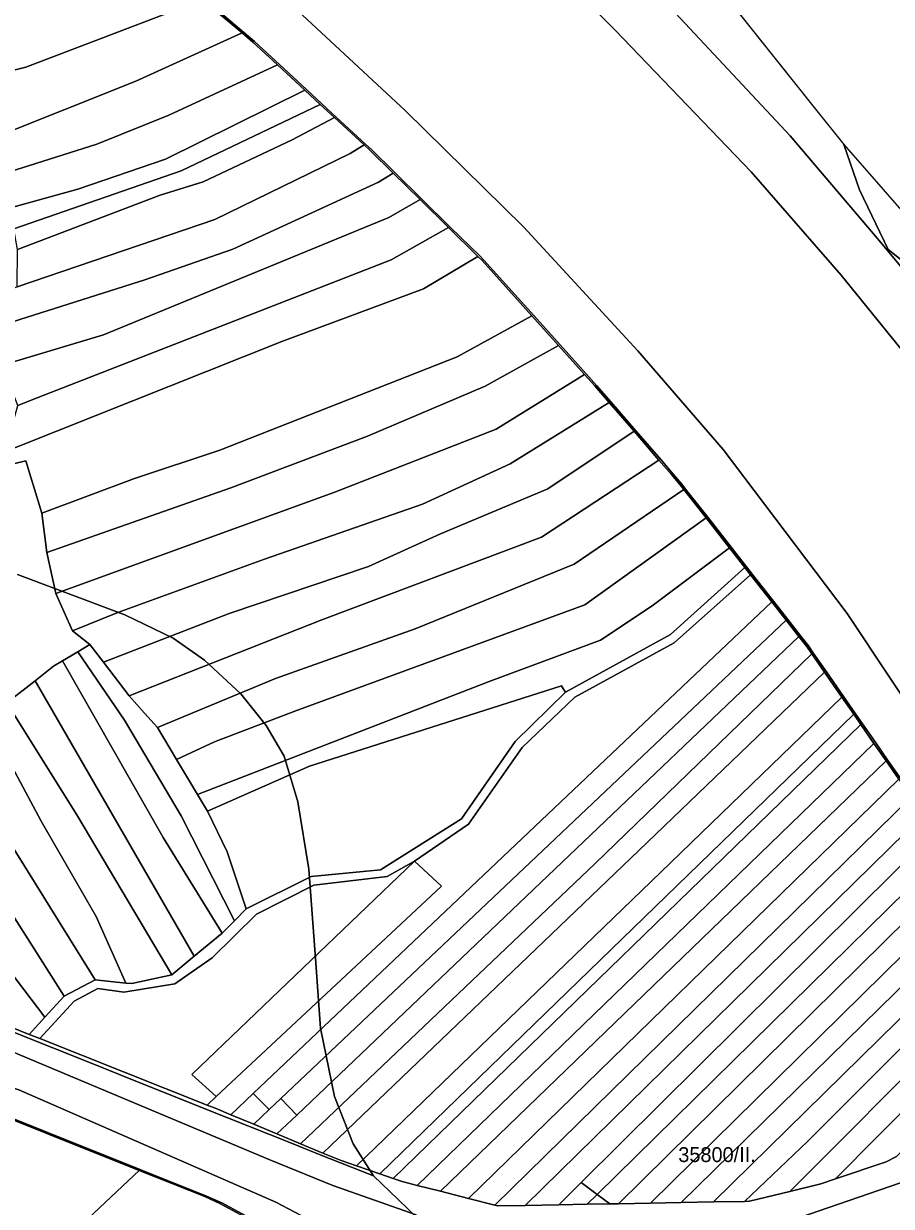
# Model space of a CAD drawing. Extents: x -535894 to -532834, y -1165802 to -1163645.
# Drawn here: x -533493.1 to -533201.8, y -1164904.7 to -1164507.5 of the extents above; entities that cross this region are included whole.
import ezdxf

# ---------------------------------------------------------------- set-up
doc = ezdxf.new("R2010")
doc.units = 0
for name, color, linetype in [('95560013', 7, 'Continuous'), ('95620013', 7, 'Continuous'), ('95630013', 7, 'Continuous'), ('95640013', 7, 'Continuous'), ('95660013', 7, 'Continuous')]:
    doc.layers.add(name, color=color, linetype=linetype)

msp = doc.modelspace()

# ---------------------------------------------------------------- linework, layer by layer
at = {"layer": '95560013'}
for points in [[(-533447.72, -1164486.86), (-533433.01, -1164499.36), (-533492.42, -1164522.13), (-533506.35, -1164525.6), (-533512.72, -1164527.18), (-533514.33, -1164516.05), (-533514.81, -1164505.48), (-533507.3, -1164504.04), (-533490.83, -1164500.89)], [(-533433.01, -1164499.36), (-533419.75, -1164510.6), (-533455.4, -1164526.78), (-533503.24, -1164545.82), (-533509.63, -1164548.37), (-533511.85, -1164533.08), (-533512.72, -1164527.18), (-533506.35, -1164525.6), (-533492.42, -1164522.13)], [(-533419.75, -1164510.6), (-533416.13, -1164513.68), (-533407.83, -1164521.35), (-533444.37, -1164538.23), (-533468.54, -1164547.91), (-533500.27, -1164558.03), (-533507.88, -1164560.46), (-533509.45, -1164549.59), (-533509.63, -1164548.37), (-533503.24, -1164545.82), (-533455.4, -1164526.78)], [(-533398.68, -1164529.8), (-533393.52, -1164534.57), (-533440.24, -1164556.89), (-533496.35, -1164576.4), (-533497.52, -1164569.37), (-533474.92, -1164563.03), (-533445.51, -1164552.98)], [(-533393.52, -1164534.57), (-533388.71, -1164539.01), (-533402.94, -1164546.53), (-533432.79, -1164560.58), (-533447.24, -1164565.04), (-533495.2, -1164583.32), (-533496.35, -1164576.4), (-533440.24, -1164556.89)], [(-533402.94, -1164546.53), (-533388.71, -1164539.01), (-533378.75, -1164548.22), (-533383.41, -1164551.04), (-533428.88, -1164573.23), (-533495.32, -1164595.82), (-533495.2, -1164583.32), (-533447.24, -1164565.04), (-533432.79, -1164560.58)], [(-533378.75, -1164548.22), (-533376.87, -1164549.96), (-533369.01, -1164557.68), (-533373.96, -1164560.66), (-533422.88, -1164583.17), (-533452.46, -1164593.56), (-533494.34, -1164606.84), (-533502.79, -1164609.52), (-533503.46, -1164599.6), (-533503.53, -1164598.61), (-533495.32, -1164595.82), (-533428.88, -1164573.23), (-533383.41, -1164551.04)], [(-533373.96, -1164560.66), (-533369.01, -1164557.68), (-533359.97, -1164566.56), (-533370.48, -1164572.58), (-533466.31, -1164612), (-533493.18, -1164620), (-533500.35, -1164622.14), (-533502.26, -1164617.26), (-533502.79, -1164609.52), (-533494.34, -1164606.84), (-533452.46, -1164593.56), (-533422.88, -1164583.17)], [(-533370.48, -1164572.58), (-533359.97, -1164566.56), (-533350.43, -1164575.94), (-533369.65, -1164586.83), (-533488.54, -1164633.13), (-533495.05, -1164635.67), (-533500.35, -1164622.14), (-533493.18, -1164620), (-533466.31, -1164612)], [(-533350.43, -1164575.94), (-533340.54, -1164585.66), (-533358.81, -1164596.53), (-533406.4, -1164614.18), (-533494.36, -1164649.22), (-533499.25, -1164651.17), (-533495.05, -1164635.67), (-533488.54, -1164633.13), (-533369.65, -1164586.83)], [(-533340.54, -1164585.66), (-533339.13, -1164587.05), (-533322.44, -1164605.61), (-533347.58, -1164619.33), (-533427.18, -1164650.69), (-533455.83, -1164660.22), (-533487.01, -1164671.82), (-533492.36, -1164654.31), (-533500.62, -1164656.25), (-533499.25, -1164651.17), (-533494.36, -1164649.22), (-533406.4, -1164614.18), (-533358.81, -1164596.53)], [(-533322.44, -1164605.61), (-533313.54, -1164615.51), (-533338.15, -1164629.18), (-533377.68, -1164645.97), (-533423.57, -1164663.33), (-533485.32, -1164685.09), (-533487.01, -1164671.82), (-533455.83, -1164660.22), (-533427.18, -1164650.69), (-533347.58, -1164619.33)], [(-533313.54, -1164615.51), (-533304.78, -1164625.25), (-533334.44, -1164643.61), (-533388.98, -1164664.88), (-533482.26, -1164698.81), (-533485.32, -1164685.09), (-533423.57, -1164663.33), (-533377.68, -1164645.97), (-533338.15, -1164629.18)], [(-533304.78, -1164625.25), (-533301.29, -1164629.13), (-533296.52, -1164634.66), (-533329.78, -1164655.32), (-533359.19, -1164668.82), (-533412.28, -1164687.27), (-533461.47, -1164705.24), (-533476.71, -1164711.39), (-533482.26, -1164698.81), (-533388.98, -1164664.88), (-533334.44, -1164643.61)], [(-533288.14, -1164644.37), (-533317.08, -1164663.67), (-533353.14, -1164678.82), (-533377.32, -1164689.81), (-533424.1, -1164705.54), (-533466.29, -1164721.94), (-533470.86, -1164715.95), (-533476.71, -1164711.39), (-533461.47, -1164705.24), (-533412.28, -1164687.27), (-533359.19, -1164668.82), (-533329.78, -1164655.32), (-533296.52, -1164634.66)], [(-533279.79, -1164654.05), (-533319.2, -1164679.92), (-533393, -1164707.69), (-533457.69, -1164733.24), (-533466.29, -1164721.94), (-533424.1, -1164705.54), (-533377.32, -1164689.81), (-533353.14, -1164678.82), (-533317.08, -1164663.67), (-533288.14, -1164644.37)], [(-533492.36, -1164654.31), (-533487.01, -1164671.82), (-533485.32, -1164685.09), (-533482.26, -1164698.81), (-533476.71, -1164711.39), (-533470.86, -1164715.95), (-533474.96, -1164718.4), (-533480.08, -1164721.45), (-533483.04, -1164723.22), (-533489.28, -1164728.14), (-533498.69, -1164735.57), (-533505.89, -1164740.44), (-533510.96, -1164745.02), (-533514.36, -1164748.08), (-533533.54, -1164686.07), (-533538.54, -1164665.37), (-533533.28, -1164663.93), (-533533.01, -1164663.86), (-533500.62, -1164656.25)], [(-533275.61, -1164658.9), (-533272.67, -1164662.3), (-533271.44, -1164663.87), (-533308.24, -1164688.97), (-533361.65, -1164710.75), (-533408.54, -1164727.43), (-533448.21, -1164743.81), (-533452.5, -1164739.03), (-533457.69, -1164733.24), (-533393, -1164707.69), (-533319.2, -1164679.92), (-533279.79, -1164654.05)], [(-533263.96, -1164673.42), (-533304.62, -1164702.63), (-533402.02, -1164738.38), (-533429.04, -1164748.7), (-533441.74, -1164754.6), (-533448.21, -1164743.81), (-533408.54, -1164727.43), (-533361.65, -1164710.75), (-533308.24, -1164688.97), (-533271.44, -1164663.87)], [(-533256.12, -1164683.46), (-533282.08, -1164703), (-533299.42, -1164714.57), (-533336.81, -1164728.38), (-533434.73, -1164766.3), (-533441.74, -1164754.6), (-533429.04, -1164748.7), (-533402.02, -1164738.38), (-533304.62, -1164702.63), (-533263.96, -1164673.42)], [(-533250.95, -1164690.07), (-533275.95, -1164712.64), (-533311.18, -1164731.99), (-533311.82, -1164730.97), (-533312.53, -1164729.81), (-533397.17, -1164756.86), (-533431.33, -1164771.97), (-533434.73, -1164766.3), (-533336.81, -1164728.38), (-533299.42, -1164714.57), (-533282.08, -1164703), (-533256.12, -1164683.46)], [(-533249.02, -1164692.52), (-533274.65, -1164715.44), (-533308.05, -1164733.69), (-533325.72, -1164750.58), (-533343.74, -1164776.33), (-533361.85, -1164788.7), (-533371.03, -1164793.86), (-533395.69, -1164796.81), (-533414.89, -1164806.5), (-533429.78, -1164821.14), (-533442.29, -1164829.96), (-533459.47, -1164832.75), (-533468.18, -1164831.46), (-533476.1, -1164835.72), (-533487.68, -1164848.33), (-533491.23, -1164846.91), (-533485.98, -1164841.17), (-533479.52, -1164834.02), (-533469.04, -1164828.56), (-533458.74, -1164829.65), (-533456.82, -1164829.86), (-533443.36, -1164826.95), (-533435.81, -1164820.69), (-533426.45, -1164812.95), (-533422.33, -1164808.76), (-533418.38, -1164804.75), (-533396.57, -1164793.83), (-533373.28, -1164791.61), (-533346.13, -1164774.47), (-533328.04, -1164748.55), (-533311.18, -1164731.99), (-533275.95, -1164712.64), (-533250.95, -1164690.07)], [(-533249.02, -1164692.52), (-533241.91, -1164701.61), (-533416.06, -1164866.8), (-533423.51, -1164873.88), (-533428.43, -1164871.84), (-533431.47, -1164870.62), (-533428.45, -1164867.8), (-533352.76, -1164797.14), (-533361.85, -1164788.7), (-533343.74, -1164776.33), (-533325.72, -1164750.58), (-533308.05, -1164733.69), (-533274.65, -1164715.44)], [(-533237.07, -1164707.79), (-533406.74, -1164868.43), (-533410.69, -1164872.17), (-533416.06, -1164866.8), (-533241.91, -1164701.61)], [(-533232.82, -1164713.23), (-533401.39, -1164873.99), (-533406.74, -1164868.43), (-533237.07, -1164707.79)], [(-533230.18, -1164716.6), (-533228.43, -1164719.12), (-533301.21, -1164789.57), (-533400.11, -1164883.63), (-533408.04, -1164880.32), (-533401.39, -1164873.99), (-533232.82, -1164713.23)], [(-533474.96, -1164718.4), (-533459.21, -1164741.38), (-533440.21, -1164773.49), (-533422.33, -1164808.76), (-533426.45, -1164812.95), (-533446.26, -1164780.81), (-533480.08, -1164721.45)], [(-533470.86, -1164715.95), (-533466.29, -1164721.94), (-533457.69, -1164733.24), (-533452.5, -1164739.03), (-533448.21, -1164743.81), (-533441.74, -1164754.6), (-533434.73, -1164766.3), (-533431.33, -1164771.97), (-533424.81, -1164785.55), (-533418.38, -1164804.75), (-533422.33, -1164808.76), (-533440.21, -1164773.49), (-533459.21, -1164741.38), (-533474.96, -1164718.4)], [(-533224.16, -1164725.28), (-533286.57, -1164785.1), (-533392.63, -1164886.74), (-533400.11, -1164883.63), (-533301.21, -1164789.57), (-533228.43, -1164719.12)], [(-533480.08, -1164721.45), (-533446.26, -1164780.81), (-533426.45, -1164812.95), (-533435.81, -1164820.69), (-533489.28, -1164728.14), (-533483.04, -1164723.22)], [(-533218.37, -1164733.63), (-533279.2, -1164792.37), (-533381.38, -1164891.04), (-533386.52, -1164889.28), (-533392.63, -1164886.74), (-533286.57, -1164785.1), (-533224.16, -1164725.28)], [(-533489.28, -1164728.14), (-533435.81, -1164820.69), (-533443.36, -1164826.95), (-533474.92, -1164773.7), (-533498.69, -1164735.57)], [(-533311.82, -1164730.97), (-533311.18, -1164731.99), (-533328.04, -1164748.55), (-533346.13, -1164774.47), (-533373.28, -1164791.61), (-533396.57, -1164793.83), (-533418.38, -1164804.75), (-533424.81, -1164785.55), (-533431.33, -1164771.97), (-533397.17, -1164756.86), (-533312.53, -1164729.81)], [(-533214.36, -1164739.41), (-533373.49, -1164893.74), (-533381.38, -1164891.04), (-533279.2, -1164792.37), (-533218.37, -1164733.63)], [(-533498.69, -1164735.57), (-533474.92, -1164773.7), (-533443.36, -1164826.95), (-533456.82, -1164829.86), (-533458.74, -1164829.65), (-533468.79, -1164807.32), (-533487.2, -1164775.28), (-533505.89, -1164740.44)], [(-533212, -1164742.81), (-533369.05, -1164895.26), (-533373.49, -1164893.74), (-533214.36, -1164739.41)], [(-533505.89, -1164740.44), (-533487.2, -1164775.28), (-533468.79, -1164807.32), (-533458.74, -1164829.65), (-533469.04, -1164828.56), (-533497.51, -1164782.8), (-533502.66, -1164774.54), (-533516.33, -1164749.86), (-533514.36, -1164748.08), (-533510.96, -1164745.02)], [(-533207.59, -1164749.17), (-533360.93, -1164897.6), (-533365.96, -1164896.32), (-533369.05, -1164895.26), (-533212, -1164742.81)], [(-533516.33, -1164749.86), (-533502.66, -1164774.54), (-533497.51, -1164782.8), (-533469.04, -1164828.56), (-533479.52, -1164834.02), (-533502.68, -1164797.66), (-533502.89, -1164782), (-533508.81, -1164787.07), (-533525.31, -1164757.95)], [(-533203.5, -1164755.07), (-533353.15, -1164899.58), (-533360.93, -1164897.6), (-533207.59, -1164749.17)], [(-533199.21, -1164761.24), (-533343.76, -1164901.98), (-533353.15, -1164899.58), (-533203.5, -1164755.07)], [(-533195.08, -1164767.19), (-533334.89, -1164904.23), (-533343.76, -1164901.98), (-533199.21, -1164761.24)], [(-533190.93, -1164773.16), (-533324.7, -1164904.32), (-533333.91, -1164904.48), (-533334.89, -1164904.23), (-533195.08, -1164767.19)], [(-533187.91, -1164777.51), (-533187.14, -1164778.93), (-533305.88, -1164896.66), (-533313.39, -1164904.12), (-533324.7, -1164904.32), (-533190.93, -1164773.16)], [(-533183.43, -1164785.63), (-533300.56, -1164900.63), (-533305.88, -1164896.66), (-533187.14, -1164778.93)], [(-533179.93, -1164791.97), (-533293.4, -1164903.76), (-533296.3, -1164903.82), (-533300.56, -1164900.63), (-533183.43, -1164785.63)], [(-533371.03, -1164793.86), (-533361.85, -1164788.7), (-533436.64, -1164860.32), (-533428.45, -1164867.8), (-533431.47, -1164870.62), (-533487.68, -1164848.33), (-533476.1, -1164835.72), (-533468.18, -1164831.46), (-533459.47, -1164832.75), (-533442.29, -1164829.96), (-533429.78, -1164821.14), (-533414.89, -1164806.5), (-533395.69, -1164796.81)], [(-533361.85, -1164788.7), (-533352.76, -1164797.14), (-533428.45, -1164867.8), (-533436.64, -1164860.32)], [(-533176.14, -1164798.83), (-533282.57, -1164903.56), (-533293.4, -1164903.76), (-533179.93, -1164791.97)], [(-533502.68, -1164797.66), (-533479.52, -1164834.02), (-533485.98, -1164841.17), (-533502.38, -1164819.76)], [(-533172.45, -1164805.52), (-533272.33, -1164903.38), (-533282.57, -1164903.56), (-533176.14, -1164798.83)], [(-533168.77, -1164812.17), (-533261.52, -1164903.19), (-533272.33, -1164903.38), (-533172.45, -1164805.52)], [(-533165.34, -1164818.38), (-533229.86, -1164882.85), (-533251.03, -1164902.99), (-533261.52, -1164903.19), (-533168.77, -1164812.17)], [(-533163.04, -1164822.52), (-533161.85, -1164825.47), (-533182.9, -1164846.57), (-533235.8, -1164899.62), (-533249.36, -1164902.96), (-533251.03, -1164902.99), (-533229.86, -1164882.85), (-533165.34, -1164818.38)], [(-533502.38, -1164819.76), (-533485.98, -1164841.17), (-533491.23, -1164846.91), (-533497.24, -1164844.53), (-533502.24, -1164838.41), (-533502.15, -1164836.07)], [(-533158.74, -1164833.17), (-533177.43, -1164852), (-533220.52, -1164895.43), (-533225.42, -1164897.07), (-533235.8, -1164899.62), (-533182.9, -1164846.57), (-533161.85, -1164825.47)], [(-533170.75, -1164858.64), (-533192.13, -1164880.06), (-533200, -1164887.93), (-533203.49, -1164889.74), (-533220.52, -1164895.43), (-533177.43, -1164852)], [(-533410.69, -1164872.17), (-533415.86, -1164877.07), (-533423.51, -1164873.88), (-533416.06, -1164866.8)], [(-533410.69, -1164872.17), (-533406.74, -1164868.43), (-533401.39, -1164873.99), (-533408.04, -1164880.32), (-533415.86, -1164877.07)], [(-533305.88, -1164896.66), (-533300.56, -1164900.63), (-533303.94, -1164903.95), (-533313.39, -1164904.12)], [(-533300.56, -1164900.63), (-533296.3, -1164903.82), (-533303.94, -1164903.95)]]:
    msp.add_lwpolyline(points, close=True, dxfattribs=at)
msp.add_lwpolyline([(-533654.62, -1164594.05), (-533574.7, -1164568.08), (-533537.72, -1164557.6), (-533509.45, -1164549.59), (-533507.88, -1164560.46), (-533500.27, -1164558.03), (-533468.54, -1164547.91), (-533444.37, -1164538.23), (-533407.83, -1164521.35), (-533398.68, -1164529.8), (-533445.51, -1164552.98), (-533474.92, -1164563.03), (-533497.52, -1164569.37), (-533506.22, -1164571.81), (-533505.11, -1164579.45), (-533504.57, -1164583.13), (-533535.82, -1164590.96), (-533555.71, -1164595.96), (-533620.26, -1164616.82), (-533719.31, -1164651.45)], dxfattribs=at)
at = {"layer": '95620013'}
for points in [[(-533217.69, -1164548.05), (-533165.64, -1164607.65), (-533177.04, -1164603.82), (-533202.85, -1164583.35), (-533212.4, -1164563.33)], [(-533516.99, -1164867.54), (-533454.32, -1164892.58), (-533497.72, -1164933.47), (-533522.7, -1164887.69), (-533553.28, -1164851.89)]]:
    msp.add_lwpolyline(points, close=True, dxfattribs=at)
at = {"layer": '95630013'}
for points in [[(-533323.6, -1164480.19), (-533294.45, -1164509.67), (-533248.86, -1164557.23), (-533218.62, -1164591.93), (-533187.88, -1164629.82)], [(-533174.44, -1164769.08), (-533216.56, -1164705.51), (-533258.18, -1164650.51), (-533286.88, -1164617.4), (-533325.21, -1164575.74), (-533365.03, -1164536.67), (-533404.17, -1164500.26)], [(-533497.24, -1164844.53), (-533491.23, -1164846.91), (-533487.68, -1164848.33), (-533431.47, -1164870.62), (-533428.43, -1164871.84), (-533423.51, -1164873.88), (-533415.86, -1164877.07), (-533408.04, -1164880.32), (-533400.11, -1164883.63), (-533392.63, -1164886.74), (-533386.52, -1164889.28), (-533381.38, -1164891.04), (-533373.49, -1164893.74), (-533369.05, -1164895.26), (-533365.96, -1164896.32), (-533360.93, -1164897.6), (-533353.15, -1164899.58), (-533343.76, -1164901.98), (-533334.89, -1164904.23), (-533333.91, -1164904.48), (-533324.7, -1164904.32), (-533313.39, -1164904.12), (-533303.94, -1164903.95), (-533296.3, -1164903.82), (-533293.4, -1164903.76), (-533282.57, -1164903.56), (-533272.33, -1164903.38), (-533261.52, -1164903.19), (-533251.03, -1164902.99), (-533249.36, -1164902.96), (-533235.8, -1164899.62), (-533225.42, -1164897.07), (-533220.52, -1164895.43), (-533203.49, -1164889.74), (-533200, -1164887.93)], [(-533361.33, -1164907.54), (-533389.23, -1164897.67), (-533410.4, -1164889.02), (-533505.42, -1164849.16)], [(-533192.2, -1164894.47), (-533236.41, -1164909.7)]]:
    msp.add_lwpolyline(points, dxfattribs=at)
at = {"layer": '95640013'}
msp.add_lwpolyline([(-533286.31, -1164461.99), (-533266.97, -1164486.26), (-533227.22, -1164536.15), (-533217.69, -1164548.05), (-533212.4, -1164563.33), (-533202.85, -1164583.35), (-533177.04, -1164603.82), (-533165.64, -1164607.65), (-533127.31, -1164620.51), (-533116.98, -1164633.6), (-533177.92, -1164613.75), (-533205.86, -1164580.27), (-533235.68, -1164545.17), (-533280.62, -1164497.03), (-533292.65, -1164484.53)], close=True, dxfattribs=at)
for points in [[(-533187.88, -1164629.82), (-533218.62, -1164591.93), (-533248.86, -1164557.23), (-533294.45, -1164509.67), (-533323.6, -1164480.19)], [(-533280.62, -1164497.03), (-533235.68, -1164545.17), (-533205.86, -1164580.27), (-533177.92, -1164613.75)], [(-533199.21, -1164761.24), (-533203.5, -1164755.07), (-533207.59, -1164749.17), (-533212, -1164742.81), (-533214.36, -1164739.41), (-533218.37, -1164733.63), (-533224.16, -1164725.28), (-533228.43, -1164719.12), (-533230.18, -1164716.6), (-533232.82, -1164713.23), (-533237.07, -1164707.79), (-533241.91, -1164701.61), (-533249.02, -1164692.52), (-533250.95, -1164690.07), (-533256.12, -1164683.46), (-533263.96, -1164673.42), (-533271.44, -1164663.87), (-533272.67, -1164662.3), (-533275.61, -1164658.9), (-533279.79, -1164654.05), (-533288.14, -1164644.37), (-533296.52, -1164634.66), (-533301.29, -1164629.13), (-533304.78, -1164625.25), (-533313.54, -1164615.51), (-533322.44, -1164605.61), (-533339.13, -1164587.05), (-533340.54, -1164585.66), (-533350.43, -1164575.94), (-533359.97, -1164566.56), (-533369.01, -1164557.68), (-533376.87, -1164549.96), (-533378.75, -1164548.22), (-533388.71, -1164539.01), (-533393.52, -1164534.57), (-533398.68, -1164529.8), (-533407.83, -1164521.35), (-533416.13, -1164513.68), (-533419.75, -1164510.6), (-533433.01, -1164499.36)], [(-533404.17, -1164500.26), (-533365.03, -1164536.67), (-533325.21, -1164575.74), (-533286.88, -1164617.4), (-533258.18, -1164650.51), (-533216.56, -1164705.51), (-533174.44, -1164769.08)], [(-533391.45, -1164912.18), (-533408.38, -1164903.25), (-533494.69, -1164865.48), (-533506.09, -1164862.02), (-533509.4, -1164860.71), (-533541, -1164847.96), (-533589.21, -1164829.81), (-533588.65, -1164829.05), (-533592.94, -1164827.83), (-533586.92, -1164822.66), (-533582.32, -1164824.01), (-533582.21, -1164823.17), (-533586.7, -1164821.82), (-533578.89, -1164821.11), (-533562.74, -1164826), (-533505.42, -1164849.16), (-533410.4, -1164889.02), (-533389.23, -1164897.67), (-533361.33, -1164907.54)], [(-533369.34, -1164934.9), (-533427.21, -1164903.65), (-533432.31, -1164901.38), (-533454.32, -1164892.58), (-533516.99, -1164867.54), (-533553.28, -1164851.89), (-533596.46, -1164833.25), (-533594.6, -1164830.75), (-533593.06, -1164828.7), (-533589.21, -1164829.81), (-533541, -1164847.96), (-533509.4, -1164860.71), (-533506.09, -1164862.02), (-533494.69, -1164865.48), (-533408.38, -1164903.25), (-533391.45, -1164912.18)], [(-533236.41, -1164909.7), (-533192.2, -1164894.47), (-533171.4, -1164881.68), (-533146.9, -1164867.45), (-533132.1, -1164861.81), (-533130.26, -1164863.56), (-533127.47, -1164863.11), (-533123.98, -1164868.64), (-533119.52, -1164875.7), (-533116.52, -1164880.45), (-533127.62, -1164885.63), (-533134.02, -1164888.62), (-533147.32, -1164895.13), (-533230.7, -1164935.9)], [(-533497.72, -1164933.47), (-533454.32, -1164892.58), (-533432.31, -1164901.38), (-533427.21, -1164903.65), (-533369.34, -1164934.9)]]:
    msp.add_lwpolyline(points, dxfattribs=at)
at = {"layer": '95660013'}
for points in [[(-533266.414, -1164486.957), (-533227.22, -1164536.15), (-533217.69, -1164548.05), (-533165.64, -1164607.65)], [(-533432.421, -1164499.181), (-533419.163, -1164510.425), (-533415.542, -1164513.504), (-533407.24, -1164521.178), (-533398.089, -1164529.631), (-533392.935, -1164534.4), (-533388.126, -1164538.839), (-533378.164, -1164548.045), (-533376.284, -1164549.784), (-533368.421, -1164557.51), (-533359.378, -1164566.393), (-533349.836, -1164575.764), (-533339.951, -1164585.487), (-533338.536, -1164586.882), (-533321.848, -1164605.439), (-533312.947, -1164615.343), (-533304.191, -1164625.08), (-533300.698, -1164628.959), (-533295.931, -1164634.49), (-533287.544, -1164644.206), (-533279.194, -1164653.887), (-533275.013, -1164658.729), (-533272.072, -1164662.135), (-533270.5, -1164664.24), (-533263.368, -1164673.254), (-533255.52, -1164683.292), (-533250.35, -1164689.904), (-533248.429, -1164692.351), (-533241.312, -1164701.443), (-533236.475, -1164707.625), (-533232.221, -1164713.068), (-533229.587, -1164716.44), (-533227.835, -1164718.959), (-533223.56, -1164725.119), (-533217.768, -1164733.469), (-533213.763, -1164739.247), (-533211.404, -1164742.648), (-533206.99, -1164749.005), (-533202.897, -1164754.903), (-533198.613, -1164761.074)], [(-533198.613, -1164761.074), (-533202.897, -1164754.903), (-533206.99, -1164749.005), (-533211.404, -1164742.648), (-533213.763, -1164739.247), (-533217.768, -1164733.469), (-533223.56, -1164725.119), (-533227.835, -1164718.959), (-533229.587, -1164716.44), (-533232.221, -1164713.068), (-533236.475, -1164707.625), (-533241.312, -1164701.443), (-533248.429, -1164692.351), (-533250.35, -1164689.904), (-533255.52, -1164683.292), (-533263.368, -1164673.254), (-533270.5, -1164664.24), (-533272.072, -1164662.135), (-533275.013, -1164658.729), (-533279.194, -1164653.887), (-533287.544, -1164644.206), (-533295.931, -1164634.49), (-533300.698, -1164628.959), (-533304.191, -1164625.08), (-533312.947, -1164615.343), (-533321.848, -1164605.439), (-533338.536, -1164586.882), (-533339.951, -1164585.487), (-533349.836, -1164575.764), (-533359.378, -1164566.393), (-533368.421, -1164557.51), (-533376.284, -1164549.784), (-533378.164, -1164548.045), (-533388.126, -1164538.839), (-533392.935, -1164534.4), (-533398.089, -1164529.631), (-533407.24, -1164521.178), (-533415.542, -1164513.504), (-533419.163, -1164510.425), (-533432.421, -1164499.181)], [(-533495.14, -1164692.5), (-533481.15, -1164697.769), (-533459.171, -1164706.05), (-533442.921, -1164713.859), (-533432.41, -1164721.18), (-533420.14, -1164732.49), (-533411.7, -1164743.171), (-533405.65, -1164753.52), (-533401.03, -1164768.81), (-533397.377, -1164791.431), (-533395.133, -1164821.465), (-533393.39, -1164844.791), (-533388.77, -1164867.72), (-533382.4, -1164883.65), (-533375.59, -1164894.45), (-533394.048, -1164887.08), (-533403.749, -1164883.207), (-533424.899, -1164874.762), (-533457.69, -1164861.67), (-533467.869, -1164857.606), (-533498.791, -1164845.26)], [(-533356.59, -1164912.8), (-533367.42, -1164902.28), (-533375.59, -1164894.45), (-533382.4, -1164883.65), (-533388.77, -1164867.72), (-533393.39, -1164844.791), (-533395.133, -1164821.465), (-533397.377, -1164791.431), (-533401.03, -1164768.81), (-533405.65, -1164753.52), (-533411.7, -1164743.171), (-533420.14, -1164732.49), (-533432.41, -1164721.18), (-533442.921, -1164713.859), (-533459.171, -1164706.05), (-533481.15, -1164697.769), (-533495.14, -1164692.5)], [(-533596.75, -1164919.33), (-533599.37, -1164895.361), (-533605.11, -1164874.33), (-533611.08, -1164860.71), (-533623.11, -1164844.309), (-533616.1, -1164842.48), (-533609.01, -1164839.53), (-533601.6, -1164834.59), (-533592.05, -1164826.55), (-533583.027, -1164818), (-533582.89, -1164817.87), (-533582.452, -1164818), (-533543.229, -1164829.65), (-533540.07, -1164830.759), (-533498.791, -1164845.26), (-533467.869, -1164857.606), (-533457.69, -1164861.67), (-533424.899, -1164874.762), (-533403.749, -1164883.207), (-533394.048, -1164887.08), (-533375.59, -1164894.45), (-533367.42, -1164902.28), (-533356.59, -1164912.8)], [(-533382.308, -1164927.394), (-533426.603, -1164903.475), (-533431.702, -1164901.198), (-533444.833, -1164895.95), (-533453.712, -1164892.401), (-533516.384, -1164867.359), (-533552.673, -1164851.701), (-533522.095, -1164887.508), (-533497.114, -1164933.287)], [(-533497.114, -1164933.287), (-533522.095, -1164887.508), (-533552.673, -1164851.701), (-533516.384, -1164867.359), (-533453.712, -1164892.401), (-533444.833, -1164895.95), (-533431.702, -1164901.198), (-533426.603, -1164903.475), (-533382.308, -1164927.394)]]:
    msp.add_lwpolyline(points, dxfattribs=at)

# ---------------------------------------------------------------- texts
msp.add_text('35800/II.', height=5, rotation=0, dxfattribs=at).set_placement((-533273.29, -1164889.776))

doc.saveas('drawing.dxf')
